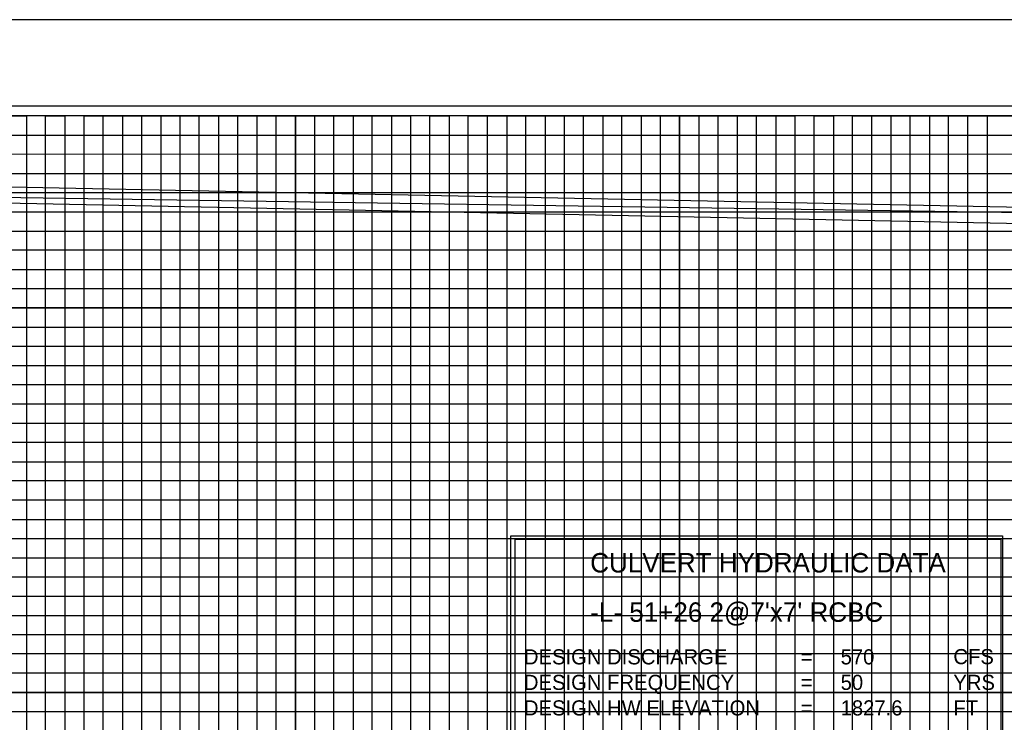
# Model space of a CAD drawing. Extents: x 557032 to 562069, y 513430 to 515874.
# Drawn here: x 558177.7 to 558433.9, y 515691.5 to 515874.3 of the extents above; entities that cross this region are included whole.
import ezdxf

# ---------------------------------------------------------------- set-up
doc = ezdxf.new("R2010")
doc.units = 0
for name, color, linetype in [('Prop Vertical Profile Curve Label', 7, 'Continuous'), ('Prop VPI Label', 7, 'Continuous'), ('Scratch_Level_5', 7, 'Continuous'), ('Sheet Cutting Line CELL', 7, 'Continuous'), ('Sheet DOT Grid CELL', 7, 'Continuous'), ('Sheet Plot Border Inside CELL', 7, 'Continuous'), ('Sheet Plot Border Outside CELL', 7, 'Continuous'), ('Sheet Profile CELL', 7, 'Continuous'), ('Sheet Profile Grid Major CELL', 7, 'Continuous'), ('Sheet Profile Grid Middle CELL', 7, 'Continuous'), ('Sheet Profile Grid Minor CELL', 7, 'Continuous')]:
    doc.layers.add(name, color=color, linetype=linetype)

msp = doc.modelspace()

# ---------------------------------------------------------------- linework, layer by layer
at = {"layer": 'Prop Vertical Profile Curve Label'}
msp.add_lwpolyline([(558305.55, 515740.01), (558433.43, 515740.01), (558433.43, 515604.72), (558305.55, 515604.72)], close=True, dxfattribs=at)
at = {"layer": 'Prop VPI Label'}
msp.add_lwpolyline([(558306.55, 515605.27), (558433.12, 515605.27), (558433.12, 515739.03), (558306.55, 515739.03)], close=True, dxfattribs=at)
at = {"layer": 'Scratch_Level_5'}
msp.add_lwpolyline([(558499.4, 515824.23), (557249.45, 515849.28), (557249.45, 515349.28), (557236.61, 515332.67), (557249.45, 515324.28), (558649.45, 515324.28), (558662.72, 515334.01), (558649.45, 515349.28), (558649.45, 515688.23), (558499.4, 515688.23)], close=True, dxfattribs=at)
for points in [[(558649.42, 515686.42), (558641.97, 515686.42), (558497.02, 515687.96), (558497.02, 515823.15), (558090.9, 515829.21), (557249.42, 515839.17)], [(558649.45, 515682.57), (558492.81, 515683.83), (558490.11, 515820.17), (558049.46, 515829.04), (557249.45, 515836.19)]]:
    msp.add_lwpolyline(points, dxfattribs=at)
at = {"layer": 'Sheet Cutting Line CELL'}
msp.add_line((558716.45, 515874.28), (557032.45, 515874.28), dxfattribs=at)
at = {"layer": 'Sheet DOT Grid CELL'}
for p, q in [((558199.45, 515349.28), (558199.45, 515849.28)), ((558249.45, 515349.28), (558249.45, 515849.28)), ((558299.45, 515349.28), (558299.45, 515849.28)), ((558349.45, 515349.28), (558349.45, 515849.28)), ((558399.45, 515349.28), (558399.45, 515849.28)), ((558499.4, 515799.28), (557199.45, 515799.28)), ((558499.4, 515749.28), (557199.45, 515749.28)), ((558499.45, 515699.28), (557199.45, 515699.28))]:
    msp.add_line(p, q, dxfattribs=at)
at = {"layer": 'Sheet Plot Border Inside CELL'}
msp.add_lwpolyline([(557045.45, 514796.73), (558711.95, 514796.73), (558711.95, 515851.83), (557045.45, 515851.83)], close=True, dxfattribs=at)
at = {"layer": 'Sheet Plot Border Outside CELL'}
msp.add_lwpolyline([(557032.45, 514774.28), (558716.45, 514774.28), (558716.45, 515874.28), (557032.45, 515874.28)], close=True, dxfattribs=at)
at = {"layer": 'Sheet Profile CELL'}
msp.add_lwpolyline([(558699.45, 515849.28), (557199.45, 515849.28), (557199.45, 514799.28), (558699.45, 514799.28)], close=True, dxfattribs=at)
at = {"layer": 'Sheet Profile Grid Major CELL'}
for points in [[(558149.45, 515349.28), (558199.45, 515349.28), (558199.45, 515849.28), (558249.45, 515849.28), (558249.45, 515349.28), (558299.45, 515349.28), (558299.45, 515849.28), (558349.45, 515849.28), (558349.45, 515349.28), (558399.45, 515349.28), (558399.45, 515849.28), (558449.45, 515849.28), (558449.45, 515349.28), (558499.45, 515349.28), (558499.45, 515849.28), (558525.75, 515849.28)], [(557199.45, 515799.28), (558499.45, 515799.28)], [(558499.45, 515749.28), (557199.45, 515749.28), (557199.45, 515699.28), (558499.45, 515699.28)]]:
    msp.add_lwpolyline(points, dxfattribs=at)
at = {"layer": 'Sheet Profile Grid Middle CELL'}
msp.add_line((557199.45, 515824.28), (558499.4, 515824.28), dxfattribs=at)
for points in [[(558174.45, 515349.28), (558224.45, 515349.28), (558224.45, 515849.28), (558274.45, 515849.28), (558274.45, 515349.28), (558324.45, 515349.28), (558324.45, 515849.28), (558374.45, 515849.28), (558374.45, 515349.28), (558424.45, 515349.28), (558424.45, 515849.28), (558474.45, 515849.28), (558474.45, 515349.28), (558524.45, 515349.28), (558524.45, 515688.23)], [(558499.45, 515774.28), (557199.45, 515774.28), (557199.45, 515724.28), (558499.45, 515724.28)]]:
    msp.add_lwpolyline(points, dxfattribs=at)
at = {"layer": 'Sheet Profile Grid Minor CELL'}
for p, q in [((557249.45, 515844.28), (558499.45, 515844.28)), ((558499.45, 515839.28), (557249.45, 515838.93)), ((557249.45, 515834.28), (558499.45, 515834.28)), ((558499.4, 515714.28), (557249.45, 515714.28)), ((558499.45, 515709.28), (557249.45, 515709.28)), ((558499.45, 515704.28), (557249.45, 515704.28)), ((557249.45, 515694.28), (558499.45, 515694.28))]:
    msp.add_line(p, q, dxfattribs=at)
for points in [[(558169.45, 515849.28), (558179.45, 515849.28), (558179.45, 515349.28)], [(558184.45, 515349.28), (558184.45, 515849.28), (558189.45, 515849.28), (558189.45, 515349.28)], [(558194.45, 515349.28), (558194.45, 515849.28), (558204.45, 515849.28), (558204.45, 515349.28)], [(558209.45, 515349.28), (558209.45, 515849.28), (558214.45, 515849.28), (558214.45, 515349.28)], [(558219.45, 515349.28), (558219.45, 515849.28), (558229.45, 515849.28), (558229.45, 515349.28)], [(558234.45, 515349.28), (558234.45, 515849.28), (558239.45, 515849.28), (558239.45, 515349.28)], [(558244.45, 515349.28), (558244.45, 515849.28), (558254.45, 515849.28), (558254.45, 515349.28)], [(558259.45, 515349.28), (558259.45, 515849.28), (558264.45, 515849.28), (558264.45, 515349.28)], [(558269.45, 515349.28), (558269.45, 515849.28), (558279.45, 515849.28), (558279.45, 515349.28)], [(558284.45, 515349.28), (558284.45, 515849.28), (558289.45, 515849.28), (558289.45, 515349.28)], [(558294.45, 515349.28), (558294.45, 515849.28), (558304.45, 515849.28), (558304.45, 515349.28)], [(558309.45, 515349.28), (558309.45, 515849.28), (558314.45, 515849.28), (558314.45, 515349.28)], [(558319.45, 515349.28), (558319.45, 515849.28), (558329.45, 515849.28), (558329.45, 515349.28)], [(558334.45, 515349.28), (558334.45, 515849.28), (558339.45, 515849.28), (558339.45, 515349.28)], [(558344.45, 515349.28), (558344.45, 515849.28), (558354.45, 515849.28), (558354.45, 515349.28)], [(558359.45, 515349.28), (558359.45, 515849.28), (558364.45, 515849.28), (558364.45, 515349.28)], [(558369.45, 515349.28), (558369.45, 515849.28), (558379.45, 515849.28), (558379.45, 515349.28)], [(558384.45, 515349.28), (558384.45, 515849.28), (558389.45, 515849.28), (558389.45, 515349.28)], [(558394.45, 515349.28), (558394.45, 515849.28), (558404.45, 515849.28), (558404.45, 515349.28)], [(558409.45, 515349.28), (558409.45, 515849.28), (558414.45, 515849.28), (558414.45, 515349.28)], [(558419.45, 515349.28), (558419.45, 515849.28), (558429.45, 515849.28), (558429.45, 515349.28)], [(558499.45, 515829.28), (557249.45, 515829.28), (557249.45, 515819.28), (558499.45, 515819.28)], [(558499.4, 515814.28), (557249.45, 515814.28), (557249.45, 515809.28), (558499.45, 515809.28)], [(558499.45, 515804.28), (557249.45, 515804.28), (557249.45, 515794.28), (558499.45, 515794.28)], [(558499.45, 515789.28), (557249.45, 515789.28), (557249.45, 515784.28), (558499.45, 515784.28)], [(558499.45, 515779.28), (557249.45, 515779.28), (557249.45, 515769.28), (558499.45, 515769.28)], [(558499.45, 515764.28), (557249.45, 515764.28), (557249.45, 515759.28), (558499.45, 515759.28)], [(558499.45, 515754.28), (557249.45, 515754.28), (557249.45, 515744.28), (558499.45, 515744.28)], [(558499.45, 515739.18), (557249.55, 515739.18), (557249.55, 515734.28), (558499.45, 515734.28)], [(558499.45, 515729.28), (557249.45, 515729.28), (557249.45, 515719.28), (558499.45, 515719.28)]]:
    msp.add_lwpolyline(points, dxfattribs=at)

# ---------------------------------------------------------------- texts
at = {"layer": 'Prop VPI Label'}
for s, height, p in [('CULVERT HYDRAULIC DATA', 5.0625, (558326.18, 515730.47)), ("-L- 51+26 2@7'x7' RCBC", 5.0625, (558326.18, 515717.63)), ('DESIGN DISCHARGE', 3.9375, (558308.92, 515706.55)), ('=     570', 3.937, (558380.96, 515706.55)), ('CFS', 3.937, (558420.69, 515706.61)), ('DESIGN FREQUENCY', 3.9375, (558308.92, 515699.91)), ('=     50', 3.937, (558380.96, 515699.91)), ('YRS', 3.937, (558420.69, 515699.91)), ('DESIGN HW ELEVATION', 3.9375, (558308.92, 515693.27)), ('=     1827.6', 3.9375, (558380.96, 515693.27)), ('FT', 3.937, (558420.69, 515693.27))]:
    msp.add_text(s, height=height, dxfattribs=at).set_placement(p)

doc.saveas('drawing.dxf')
